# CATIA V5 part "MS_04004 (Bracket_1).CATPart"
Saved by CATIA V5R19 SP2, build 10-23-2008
Part number: MS_04004
Definition: Bracket_1
Bounding box of the stored display mesh (mm): x 0 to 18.824, y 0 to 14, z 0 to 1.5
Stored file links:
  D:\Robin Niermaréchal\Documents\EPSA\03-GIT\Valkyriz\ELIZ-2021\MS_Miscellaneous_Finish_Assembly\MS_A0400 (Firewall)\Chappes\MS_04004 (Bracket_1).CATPart
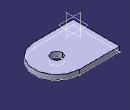
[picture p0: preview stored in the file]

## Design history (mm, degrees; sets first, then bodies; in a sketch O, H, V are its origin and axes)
SheetMetalParameters1: Thickness 1.5, BendRadius 3, KFactor 0.400515 {= log(min(100,max(20*SheetMetalParameters1.BendRadius,SheetMetalParameters1.Thickness)/SheetMetalParameters1.Thickness))/log(100)/2}, ReliefRadialLength 1, ReliefAxialLength 2, MinimumBendRadius 0
Body1 (main body)
  Sketch1 on xy-plane, origin (0, 0, 0), H (1, 0, 0), V (0, 1, 0)
    line L1 (0, 0) -> (12, 0)
    arc A1 centre (12, 7) radius 7 from (12, 0) to (12, 14) ccw
    line L2 (12, 14) -> (0, 14)
    line L3 (0, 14) -> (0, 0)
    circle A2 centre (12, 7) radius 1.7
    length L2 = 12
    length L3 = 14
    radius A2 = 1.7
    radius A1 = 7
    horizontal: L1 H
    tangency: A1 L1, L2 A1
    vertical: L3 V
  Wall1: Thickness 1.5, Profile Sketch1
